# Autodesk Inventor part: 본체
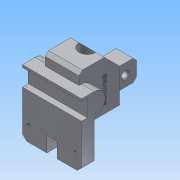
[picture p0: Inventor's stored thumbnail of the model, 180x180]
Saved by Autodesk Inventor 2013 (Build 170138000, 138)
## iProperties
Created: 2016-11
Part Number: 본체
Material: 알루미늄 6061
Document SubType Name: Modeling
Designer: Administrator
Density: 2.71 g/cm^3
Mass: 462.906 g
Surface Area: 317.29 cm^2
Volume: 170.814 cm^3
Author: Administrator
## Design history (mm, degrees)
sketch "스케치3"
  geometry: L1 (24, 29)-(-24, 29); L2 (24, -29)-(24, 29); L3 (24, 29)-(-24, -29); L4 (-24, 29)-(24, -29); L5 (-24, 29)-(-24, -61); L6 (24, -29)-(-16, -29); L7 (-16, -29)-(-16, -61); L8 (-16, -61)-(-24, -61); 1 further point
  constraints: 16 end point, 2 midpoint, 2 parallel, 2 perpendicular, 1 horizontal
  dimensions: "d11" = 48 distance of L2.start L3.end; "d12" = 58 distance of L3.end L1.end; "d13" = 90 distance of L1.end L5.end; "d14" = 8 distance between parallel lines of L5 L7; "d15" = 58 distance between parallel lines of L1 L6; "d16" = 24 distance from line of L2 point (0, 0)
extrude "돌출2" new body sketch "스케치3" stored distance "d17" = 40; taper "d18" = 0 deg
sketch "스케치4"
  geometry: L1 (24, 29)-(24, -29) reference; L2 (24, -29)-(-16, -29) reference; L3 (-16, -29)-(-16, -61) reference; L4 (-16, -61)-(-24, -61) reference; L5 (-24, -61)-(-24, 29) reference; L6 (-24, 29)-(24, 29) reference; L7 (6, 29)-(24, 11); L8 (24, 29)-(6, 29); L9 (24, 28.074)-(24, 11); 1 further point
  constraints: 6 end point, 3 point on line
  dimensions: "d19" = 30 distance from line of L5 L7.start; "d21" = 45 deg angle of L7 L1
extrude "돌출3" cut sketch "스케치4" stored distance "d22" = 100; taper "d23" = 0 deg
chamfer "모따기1" distance "d24" = 4; stored, may be unused: second distance "d25" = 2, angle "d26" = 45 deg
node "작업 평면1"
sketch "스케치5"
  geometry: L1 (-16, -29)-(24, -29) reference; L2 (24, -29)-(24, 11) reference; L3 (24, 11)-(6, 29) reference; L4 (6, 29)-(-20, 29) reference; L5 (-24, -61)-(-16, -61) reference; L6 (-21, -61)-(-36, -61); L7 (-36, -61)-(-36, -8); L8 (-36, 2)-(-21, 2); L9 (-36, 12)-(-29, 12); L10 (-29, 12)-(-29, -8); L11 (-29, -8)-(-36, -8); L12 (-21, -11)-(-21, -61); L13 (-21, 15)-(-36, 15); L14 (-36, -8)-(-36, 2); L15 (-36, 12)-(-36, 15); A1 r 13 centre (-21, 2) between (-21, -11) and (-21, 15); 1 further point
  constraints: 20 end point, 7 perpendicular, 2 point on circle, 1 centre point, 1 coincident, 1 collinear, 1 point on line, 1 tangent
  dimensions: "d28" = 26 diameter of A1; "d35" = 63 distance of L6.end L8.start; "d36" = 15 distance of L8.start L8.end; "d38" = 10 distance from line of L11 A1.centre; "d39" = 10 distance from line of L9 A1.centre; "d40" = 7 distance between parallel lines of L7 L10; "d42" = 53 distance between parallel lines of L6 L11; "d105" = 60 distance between parallel lines of L7 L2; "d106" = 15 distance between parallel lines of L7 L12; "d107" = 15 distance of L13.start L13.end
extrude "돌출4" join sketch "스케치5" distance "d43" = 70; taper "d44" = 0 deg
sketch "스케치6"
  geometry: L1 (54, 1)-(24, 1); L2 (24, -24)-(54, -24); L3 (54, -24)-(54, 1); L4 (54, 1)-(25.939, -24); L5 (25.939, 1)-(54, -24); L6 (-36, -8)-(-36, -61) reference; L7 (-16, -29)-(24, -29) reference; L8 (-24, 25)-(-20, 29) reference; L9 (-20, 29)-(6, 29) reference; L10 (6, 29)-(24, 11) reference; L11 (24, 11)-(24, -29) reference; L12 (24, -29)-(-16, -29) reference; L13 (-16, -29)-(-16, -61) reference; L14 (-16, -61)-(-36, -61) reference; L15 (-36, -61)-(-36, -8) reference; L16 (-36, -8)-(-29, -8) reference; L17 (-29, -8)-(-29, 12) reference; L18 (-29, 12)-(-36, 12) reference; L19 (-36, 12)-(-36, 15) reference; L20 (-36, 15)-(-24, 15) reference; L21 (-24, 15)-(-24, 25) reference; 2 further points
  constraints: 10 end point, 4 point on line, 2 midpoint, 1 horizontal, 1 parallel
  dimensions: "d45" = 25 distance of L2.end L1.start; "d47" = 90 distance between parallel lines of L6 L3; "d48" = 5 distance between parallel lines of L2 L7
extrude "돌출5" join sketch "스케치6" stored distance "d49" = 20; taper "d50" = 0 deg
chamfer "모따기2" distance "d51" = 4; stored, may be unused: second distance "d52" = 2, angle "d53" = 45 deg
chamfer "모따기3" distance "d54" = 5; stored, may be unused: second distance "d55" = 2, angle "d56" = 45 deg
sketch "스케치7"
  geometry: L1 (40, 0)-(0, 0) reference; L2 (-10, -20)-(50, -20) reference; L3 (14, -6.373)-(14, -20); L4 (26, -6.373)-(26, -20); A1 r 29 centre (20, 22) between (1.106, 0) and (14, -6.373); A2 r 29 centre (20, 22) between (26, -6.373) and (38.894, 0); 1 further point
  constraints: 4 end point, 4 point on circle, 4 point on line, 2 centre point, 1 parallel, 1 perpendicular, 1 vertical alignment
  dimensions: "d59" = 42 distance from line of L2 A1.centre; "d60" = 6 distance from line of L4 A1.centre; "d61" = 6 distance from line of L3 A1.centre; "d62" = 29 radius of A2; "d63" = 29 radius of A1
extrude "돌출6" cut sketch "스케치7" distance "d64" = 18; taper "d65" = 0 deg
sketch "스케치8"
  geometry: L1 (26, -60)-(50, -60) reference; 2 further points
  constraints: 1 vertical alignment
  dimensions: "d68" = 42 distance from line of L1 point (20, -18)
hole "구멍1" sketch "스케치8" at (20, -18) diameter "d69" = 20; stored, may be unused: countersink angle "d73" = 90 deg, drill point angle "d75" = 0 deg; dims "d70" = 6, "d71" = 29, "d72" = 7, "d74" = 8
sketch "스케치9"
  geometry: L1 (-1, 50)-(-1, 24) reference; L2 (8, -36)-(56, -36) reference; C1 r 4 at (11.5, 41); 2 further points
  constraints: 1 centre point
  dimensions: "d76" = 8 diameter of C1; "d77" = 12.5 distance from line of L1 C1.centre; "d78" = 77 distance from line of L2 C1.centre
extrude "돌출7" cut sketch "스케치9" stored distance "d79" = 10; taper "d80" = 0 deg
sketch "스케치10"
  geometry: L1 (29, -16)-(29, 24) reference; L2 (29, 24)-(-11, 24) reference; 2 further points
  constraints: 1 other
  dimensions: "d81" = 25 distance from line of L1 point (4, 6); "d82" = 18 distance from line of L2 point (4, 6)
feature "엠보싱1" sketch "스케치10" dims "d11" = 48, "d12" = 58, "d13" = 90, "d14" = 8, "d15" = 58, "d16" = 24, "d83" = 0.5, "d84" = 0
fillet "모깎기3" dims "d100" = 3
chamfer "모따기4" distance "d101" = 1; stored, may be unused: second distance "d102" = 2, angle "d103" = 45 deg
sketch "스케치12"
  geometry: L1 (24, 0)-(0, 0) reference; L2 (60, 0)-(36, 0) reference; 3 further points
  dimensions: "d109" = 27.5 horizontal distance of point (30, -61) point (2.5, -18); "d110" = 27.5 horizontal distance of point (57.5, -18) point (30, -61); "d111" = 18 distance from line of point (2.5, -18) L1; "d112" = 18 distance from line of point (57.5, -18) L2
hole "구멍3" sketch "스케치12" at (2.5, -18), (57.5, -18) diameter "d113" = 3.242; stored, may be unused: countersink angle "d117" = 90 deg, drill point angle "d119" = 118 deg; dims "d114" = 6, "d115" = 4, "d116" = 2, "d118" = 8
fillet "모깎기5" dims "d120" = 3
fillet "모깎기6" dims "d121" = 5
node "솔리드2"
node "절단 모서리 투영1"
node "절단 모서리 투영2"
other parameters: "d27" = 35, "d57" = 58
